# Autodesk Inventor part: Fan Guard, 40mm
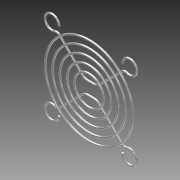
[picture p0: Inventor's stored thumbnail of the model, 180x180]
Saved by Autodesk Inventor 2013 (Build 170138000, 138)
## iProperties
Company: Autodesk Inc.
Created: 2005-12
Part Number: Fan Guard, 40mm
Document SubType Name: Modeling
Designer: Autodesk Inc.
Density: 1 g/cm^3
Mass: 0.23414 g
Surface Area: 12.309 cm^2
Volume: 0.23414 cm^3
Material: Allgemein
Title: Personal Computer
Author: Autodesk Inc.
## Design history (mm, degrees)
sketch "Sketch1"
  geometry: L1 (-13.02, 13.02)-(-3.51, 3.51) reference; L2 (-1.265, 2.58)-(1.265, 2.58); L3 (13.02, 13.02)-(3.51, 3.51) reference; L4 (0, 0)-(0, 12.139); A1 r 2.915 centre (-16, 16) between (-13.085, 16) and (-14.798, 13.344) reference; A2 r 3.175 centre (-1.265, 5.755) between (-3.51, 3.51) and (-1.265, 2.58); A3 r 1.587 centre (-14.143, 11.898) between (-13.02, 13.02) and (-14.798, 13.344); A4 r 1.587 centre (14.143, 11.898) between (14.798, 13.344) and (13.02, 13.02); A5 r 2.915 centre (16, 16) between (14.798, 13.344) and (13.085, 16) reference; A6 r 3.175 centre (1.265, 5.755) between (1.265, 2.58) and (3.51, 3.51)
  constraints: 12 point on circle, 8 end point, 6 centre point, 4 tangent, 1 perpendicular, 2 other
  dimensions: "d0" = 3.175 radius of A2; "d1" = 3.175 diameter of A3; "d10" = 2.91541 radius of A1 (derived); "d11" = 32 distance of A5.centre A1.centre; "d13" = 2.57981 distance from line of L2 L4.start
workplane "Work Plane1"
sketch "Sketch2"
  geometry: C1 r 0.381 at (0, 0)
  constraints: 1 centre point
  dimensions: "d2" = 0.762 diameter of C1
sweep "Sweep1" sketch "Sketch2" dims "d3" = 0
sketch "Sketch4"
  geometry: L1 (13.02, -13.02)-(3.51, -3.51) reference; L2 (-1.265, -2.58)-(1.265, -2.58); L3 (0, 0)-(0, -10.796); L4 (-13.02, -13.02)-(-3.51, -3.51) reference; A1 r 3.175 centre (1.265, -5.755) between (3.51, -3.51) and (1.265, -2.58); A2 r 1.587 centre (14.143, -11.898) between (13.02, -13.02) and (14.798, -13.344); A3 r 2.915 centre (16, -16) between (13.085, -16) and (14.798, -13.344) reference; A4 r 3.175 centre (-1.265, -5.755) between (-1.265, -2.58) and (-3.51, -3.51); A5 r 1.587 centre (-14.143, -11.898) between (-14.798, -13.344) and (-13.02, -13.02); A6 r 2.915 centre (-16, -16) between (-14.798, -13.344) and (-13.085, -16) reference
  constraints: 12 point on circle, 8 end point, 7 symmetric about line, 6 centre point, 1 perpendicular, 3 other
  dimensions: "d14" = 2.91541 radius of A3; "d15" = 1.5875 radius of A2; "d16" = 3.175 radius of A1; "d17" = 2.57981 distance from line of L3.start L2
workplane "Work Plane3"
sketch "Sketch5"
  geometry: C1 r 0.381 at (0, 0)
  constraints: 1 centre point
  dimensions: "d7" = 0.762 diameter of C1
sweep "Sweep2" sketch "Sketch5" dims "d8" = 0
workplane "Work Plane4"
sketch "Sketch7"
  geometry: C1 r 15 at (0, 0)
  constraints: 1 centre point
  dimensions: "d19" = 30 diameter of C1
sketch "Sketch8"
  geometry: C1 r 12 at (0, 0)
  constraints: 1 centre point
  dimensions: "d20" = 24 diameter of C1
sketch "Sketch9"
  geometry: C1 r 9 at (0, 0)
  constraints: 1 centre point
  dimensions: "d21" = 18 diameter of C1
sketch "Sketch10"
  geometry: C1 r 6 at (0, 0)
  constraints: 1 centre point
  dimensions: "d22" = 12 diameter of C1
sweep "Sweep3" dims "d28" = 0
sweep "Sweep4" dims "d29" = 0
sweep "Sweep5" dims "d30" = 0
sweep "Sweep6" dims "d31" = 0
sweep "Sweep7" dims "d32" = 0
body "Solid1"
sketch "Sketch6"
  geometry: C1 r 18 at (0, 0); 1 further point
  constraints: 1 centre point, 1 coincident
  dimensions: "d18" = 36 diameter of C1
sketch "Sketch11"
  geometry: L1 (18, 0.762)-(-18, 0.762) reference; C1 r 0.381 at (-18, 0.762); 1 further point
  constraints: 1 centre point, 1 coincident
  dimensions: "d23" = 0.762 diameter of C1
sketch "Sketch12"
  geometry: L1 (15, 0.762)-(-15, 0.762) reference; C1 r 0.381 at (-15, 0.762)
  constraints: 1 centre point, 1 coincident
  dimensions: "d24" = 0.762 diameter of C1
sketch "Sketch13"
  geometry: L1 (12, 0.762)-(-12, 0.762) reference; C1 r 0.381 at (-12, 0.762)
  constraints: 1 centre point, 1 coincident
  dimensions: "d25" = 0.762 diameter of C1
sketch "Sketch14"
  geometry: L1 (9, 0.762)-(-9, 0.762) reference; C1 r 0.381 at (-9, 0.762)
  constraints: 1 centre point, 1 coincident
  dimensions: "d26" = 0.762 diameter of C1
sketch "Sketch15"
  geometry: L1 (6, 0.762)-(-6, 0.762) reference; C1 r 0.381 at (-6, 0.762)
  constraints: 1 centre point, 1 coincident
  dimensions: "d27" = 0.762 diameter of C1
other parameters: "d9" = 0.762
